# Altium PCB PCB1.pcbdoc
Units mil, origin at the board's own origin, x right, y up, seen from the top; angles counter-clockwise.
Board outline 2870.7 x 2332.93 mil, 2 copper layers (Top Layer, Bottom Layer); 40 components, 64 nets, 418 pads, 3 vias.
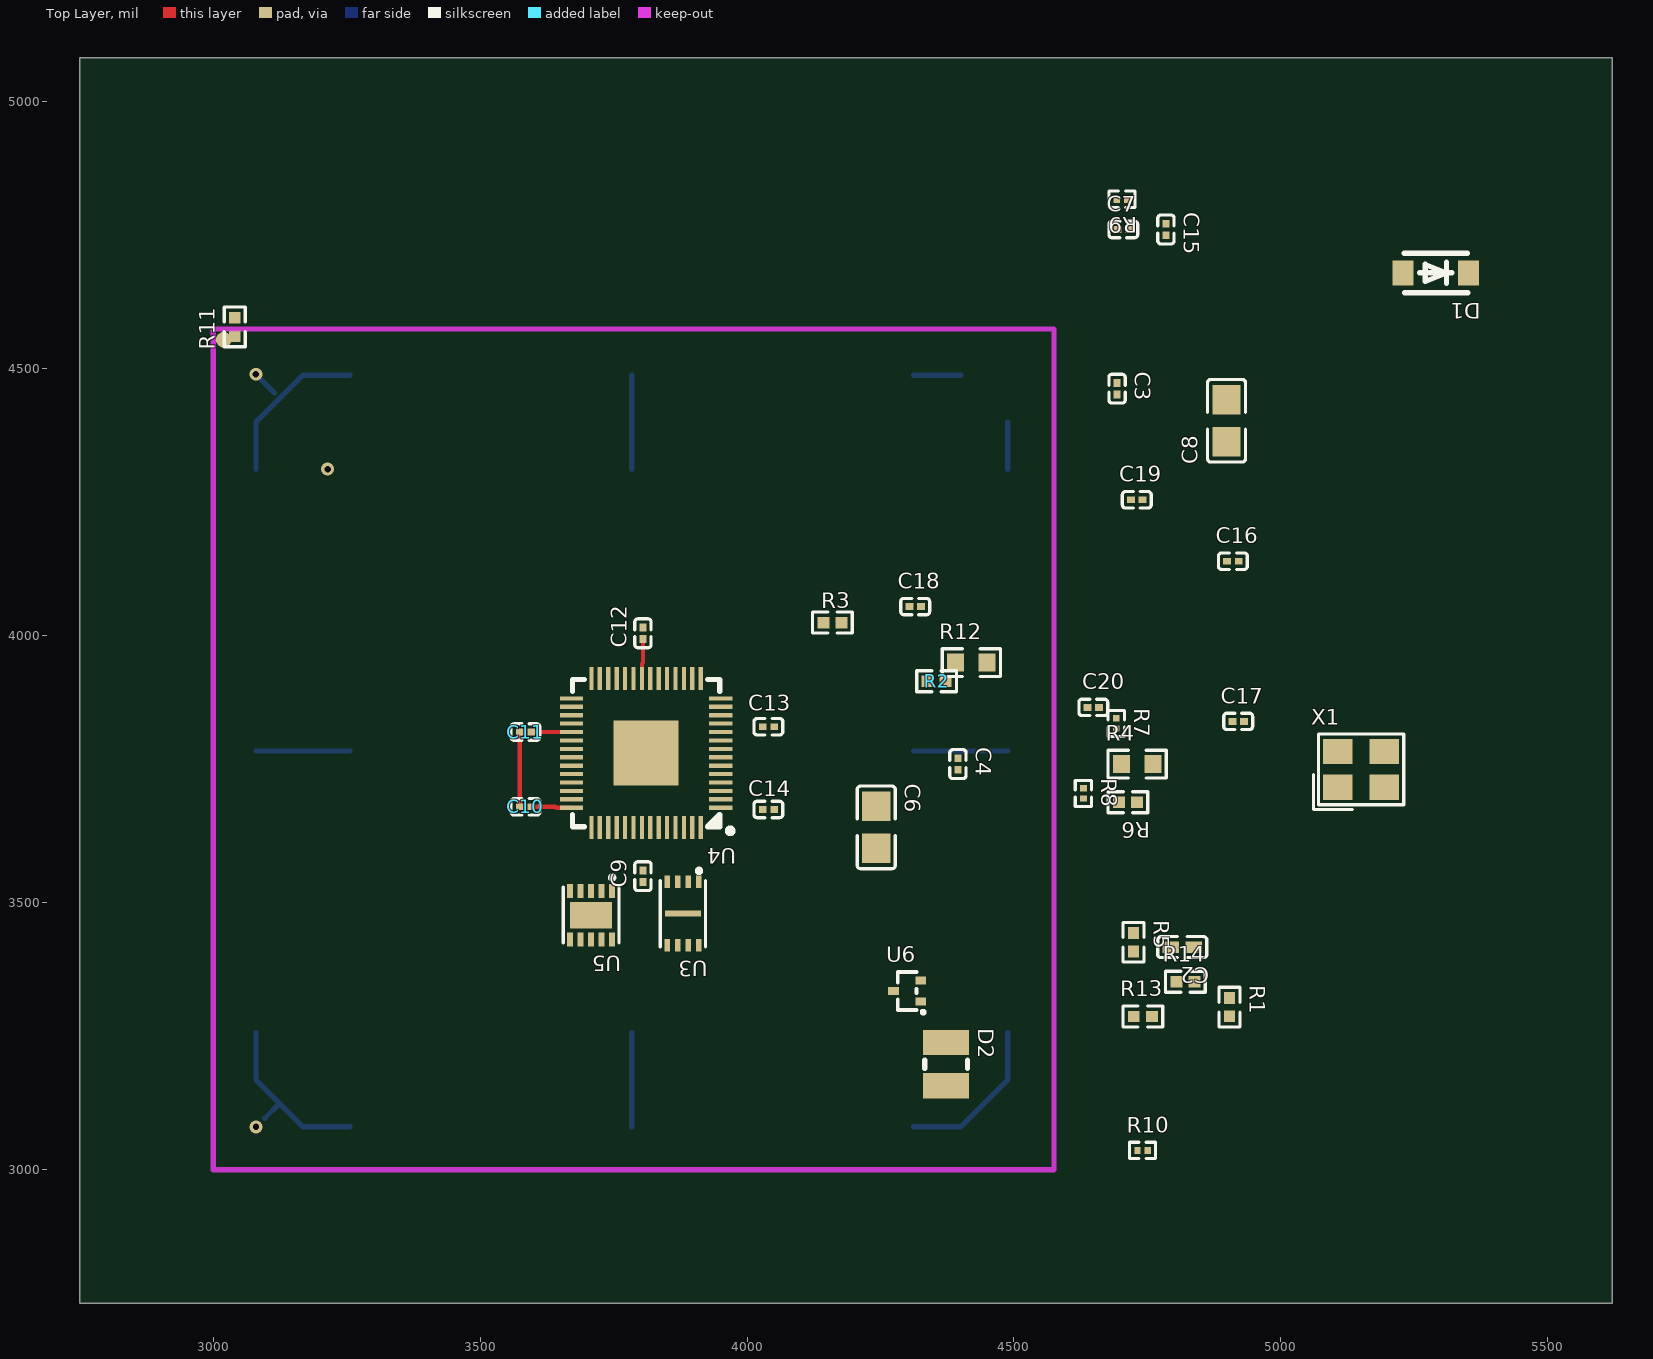
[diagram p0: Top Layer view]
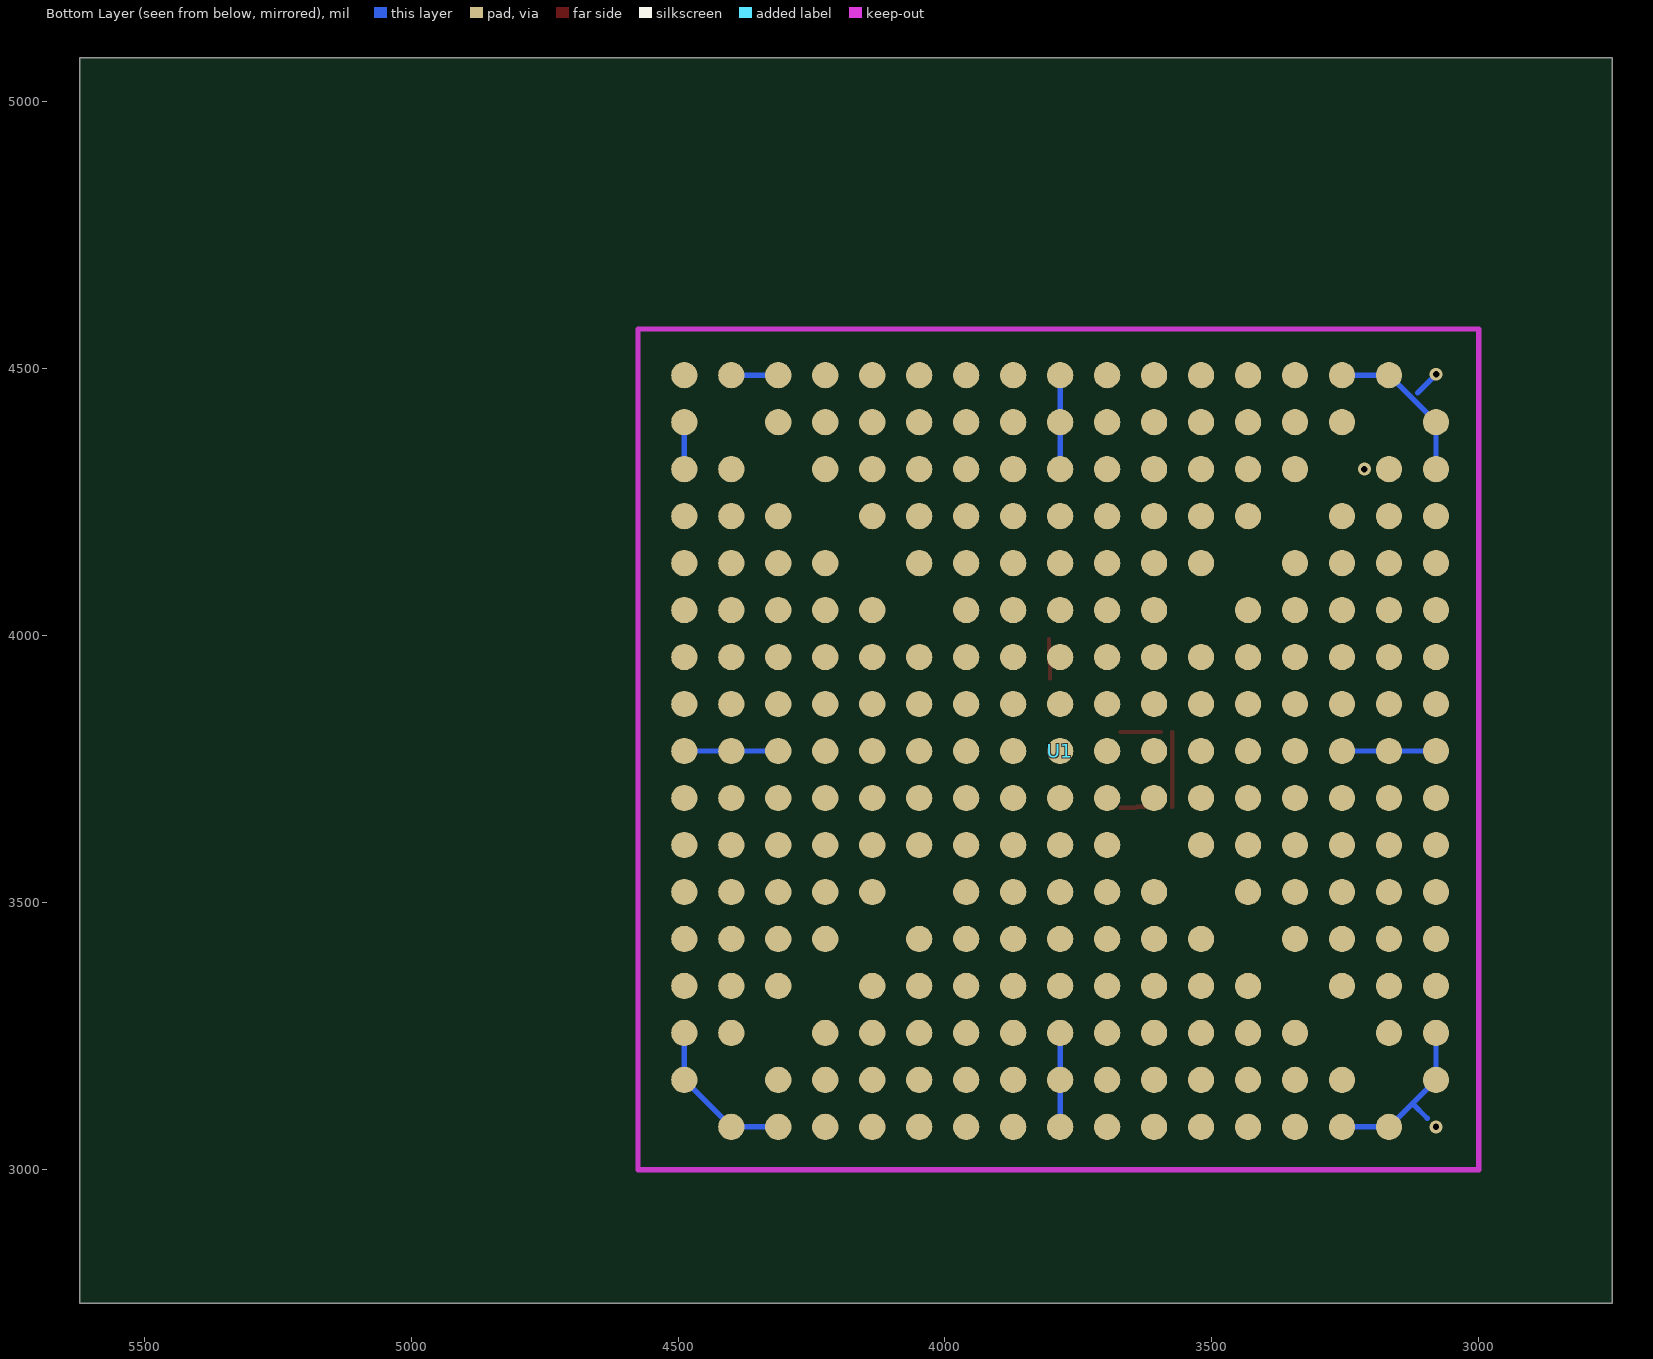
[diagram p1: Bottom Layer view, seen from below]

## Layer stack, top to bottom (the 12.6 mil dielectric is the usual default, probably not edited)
Top Layer: signal copper (thickness not stored)
Dielectric: dielectric 12.6, FR-4, Dk 4.8
Bottom Layer: signal copper (thickness not stored)

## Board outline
5620.7,2750 2750,2750 2750,5082.93 5620.7,5082.93

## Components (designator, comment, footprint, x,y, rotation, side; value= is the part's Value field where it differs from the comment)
C2 "CL05A225MQ5NSNC" C0402 4815.17,3416.97 r180 top
C3 "CL03C150JA3ANNC" C0201 4693.11,4462.99 r270 top
C4 "CL03C150JA3ANNC" C0201 4395,3759.8 r270 top
C6 "GRM21BR60J476ME01L" C0805 4242.08,3641.19 r270 top
C7 "GRM033R60J104KE19D" C0201 4704.78,4761.11 r0 top
C8 "GRM21BR60J476ME01L" C0805 4898.04,4402.83 r90 top
C9 "GRM033R60J104KE19D" C0201 3805,3549.8 r270 top
C10 "GRM033R60J104KE19D" C0201 3585,3679.8 r180 top
C11 "GRM033R60J104KE19D" C0201 3585,3819.8 r180 top
C12 "GRM033R60J104KE19D" C0201 3805,4004.8 r90 top
C13 "GRM033R60J104KE19D" C0201 4040,3829.8 r0 top
C14 "GRM033R60J104KE19D" C0201 4040,3674.8 r0 top
C15 "GRM033R60J104KE19D" C0201 4784.56,4761.11 r270 top
C16 "GRM033R60J104KE19D" C0201 4910,4139.8 r0 top
C17 "GRM033R60J104KE19D" C0201 4920,3839.8 r0 top
C18 "GRM033R60J104KE19D" C0201 4315,4054.8 r0 top
C19 "GRM033R60J104KE19D" C0201 4730,4254.8 r0 top
C20 "GRM033R71E102KA01D" C0201 4648.55,3866 r180 top
D1 "MBR120VLSFT1G" SOD-123F_L2.8-W1.8-LS3.7-RD 5290,4679.8 r180 top
D2 "SRN2512-2R2M" IND-SMD_L2.5-W2.0 4372.83,3197.93 r270 top
R1 "AECR0402F1K00K9" R0402 4903.66,3304.63 r270 top
R2 "AECR0402F1K00K9" R0402 4355,3914.8 r0 top
R3 "CR0402F5K60Q10Z" R0402 4160,4024.8 r0 top
R4 "0603WAF1002T5E" R0603 4730.78,3759.77 r0 top
R5 "RC0402FR-07100KL" R0402 4723.84,3426.01 r270 top
R6 "RC0402FR-07100KL" R0402 4713.43,3688.45 r180 top
R7 "RC0201FR-0727RL" R0201 4691.63,3835.94 r270 top
R8 "RC0201FR-0727RL" R0201 4630,3704.8 r270 top
R9 "RC0201FR-0727RL" R0201 4702.21,4817.55 r180 top
R10 "RC0201FR-0727RL" R0201 4740.75,3036.19 r0 top
R11 "RC0402FR-071RL" R0402 3040.44,4578.68 r90 top
R12 "RC0603FR-07200RL" R0603 4420,3949.8 r0 top
R13 "RC0402FR-07100KL" R0402 4741.39,3287.08 r0 top
R14 "RC0402FR-07200KL" R0402 4821.17,3352.03 r0 top
U1 "usrp2040v0" 17x17 4488.19,4488.19 r180 bottom
U3 "W25Q16JVUXIQ" USON-8_L3.0-W2.0-P0.50-BL-EP 3880,3479.8 r180 top
U4 "RP2040_C2040" LQFN-56_L7.0-W7.0-P0.4-EP 3810.91,3780.43 r180 top
U5 "RT6150BGQW" WSON-10_L2.5-W2.5-P0.50-BL-EP 3707.93,3476.87 r180 top
U6 "DMG1012T-13" SOT-523-3_L1.6-W0.8-P1.00-LS1.6-BR 4300,3334.8 r0 top
X1 "X322512MMB4SI" CRYSTAL-SMD_4P-L3.2-W2.5-BL 5150,3749.8 r0 top

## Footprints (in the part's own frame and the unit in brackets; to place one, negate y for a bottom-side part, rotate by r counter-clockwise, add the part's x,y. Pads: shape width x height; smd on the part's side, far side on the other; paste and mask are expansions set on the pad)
17x17 [mm]
  round 1.25 smd mask+0.051: BOOTSEL(22.35,-13.41) CPUEN(13.41,-13.41) DEBUGEN(13.41,-22.35) GND(0,-33.525) GND(0,-31.29) GND(0,-4.47) GND(0,-2.235) GND(2.235,-35.76) GND(2.235,0) GND(4.47,-35.76) GND(4.47,0) GND(17.88,-17.879) GND(31.29,-35.76) GND(31.29,0) GND(33.525,-35.76) GND(33.525,0) GND(35.76,-33.525) GND(35.76,-31.29) GND(35.76,-4.47) GND(35.76,-2.235) GPIO0(6.705,0) GPIO1(8.94,0) GPIO2(11.175,0) GPIO3(13.41,0) GPIO4(15.645,0) GPIO5(20.115,0) GPIO6(22.35,0) GPIO7(24.585,0) GPIO8(26.82,0) GPIO9(29.055,0) GPIO10(4.47,-2.235) GPIO11(6.705,-2.235) GPIO12(8.94,-2.235) GPIO13(11.175,-2.235) GPIO14(13.41,-2.235) GPIO15(15.645,-2.235) GPIO16(20.115,-2.235) GPIO17(22.35,-2.235) GPIO18(24.585,-2.235) GPIO19(26.82,-2.235) GPIO20(29.055,-2.235) GPIO21(31.29,-2.235) GPIO22(2.235,-4.47) GPIO23(6.705,-4.47) GPIO24(8.94,-4.47) GPIO25(11.175,-4.47) GPIO26(13.41,-4.47) GPIO27(15.645,-4.47) GPIO28(20.115,-4.47) GPIO29(22.35,-4.47) GPIO30(24.585,-4.47) GPIO31(26.82,-4.47) GPIO32(29.055,-4.47) GPIO33(33.525,-4.47) GPIO34(0,-6.705) GPIO35(2.235,-6.705) GPIO36(4.47,-6.705) GPIO37(8.94,-6.705) GPIO38(11.175,-6.705) GPIO39(13.41,-6.705) GPIO40(15.645,-6.705) GPIO41(17.88,-6.705) GPIO42(20.115,-6.705) GPIO43(22.35,-6.705) GPIO44(24.585,-6.705) GPIO45(26.82,-6.705) GPIO46(31.29,-6.705) GPIO47(33.525,-6.705) GPIO48(35.76,-6.705) GPIO49(13.41,-8.94) GPIO50(17.88,-8.94) GPIO51(33.525,-8.94) GPIO52(0,-8.94) GPIO53(2.235,-8.94) GPIO54(4.47,-8.94) GPIO55(6.705,-8.94) GPIO56(11.175,-8.94) GPIO57(31.29,-8.94) GPIO58(22.35,-8.94) GPIO59(24.585,-8.94) GPIO60(29.055,-8.94) GPIO61(15.645,-8.94) GPIO62(20.115,-8.94) GPIO63(35.76,-8.94) GPIO64(0,-11.175) GPIO65(31.29,-11.175) GPIO66(4.47,-11.175) GPIO67(6.705,-11.175) GPIO68(8.94,-11.175) GPIO69(15.645,-11.175) GPIO70(17.88,-11.175) GPIO71(26.82,-11.175) GPIO72(29.055,-11.175) GPIO73(33.525,-11.175) GPIO74(35.76,-11.175) GPIO75(2.235,-11.175) GPIO76(20.115,-11.175) GPIO77(22.35,-11.175) GPIO78(13.41,-11.175) GPIO79(11.175,-13.41) GPIO80(29.055,-13.41) GPIO81(31.29,-13.41) GPIO82(0,-13.41) GPIO83(6.705,-13.41) GPIO84(8.94,-13.41) GPIO85(15.645,-13.41) GPIO86(17.88,-13.41) GPIO87(24.585,-13.41) GPIO88(26.82,-13.41) GPIO89(33.525,-13.41) GPIO90(35.76,-13.41) GPIO91(2.235,-13.41) GPIO92(4.47,-13.41) GPIO93(20.115,-13.41) GPIO94(11.175,-15.645) GPIO95(13.41,-15.645) GPIO96(29.055,-15.645) GPIO97(31.29,-15.645) GPIO98(0,-15.645) GPIO99(6.705,-15.645) GPIO100(8.94,-15.645) GPIO101(24.585,-15.645) GPIO102(26.82,-15.645) GPIO103(33.525,-15.645) GPIO104(35.76,-15.645) GPIO105(2.235,-15.645) GPIO106(4.47,-15.645) GPIO107(22.35,-15.645) GPIO108(6.705,-17.88) GPIO109(8.94,-17.88) GPIO110(11.175,-17.88) GPIO111(13.41,-17.88) GPIO112(22.35,-17.88) GPIO113(24.585,-17.88) GPIO114(26.82,-17.88) GPIO115(29.055,-17.88) GPIO116(0,-20.115) GPIO117(2.235,-20.115) GPIO118(4.47,-20.115) GPIO119(6.705,-20.115) GPIO120(8.94,-20.115) GPIO121(11.175,-20.115) GPIO122(13.41,-20.115) GPIO123(22.35,-20.115) GPIO124(24.585,-20.115) GPIO125(26.82,-20.115) GPIO126(29.055,-20.115) GPIO127(31.29,-20.115) GPIO128(33.525,-20.115) GPIO129(35.76,-20.115) GPIO130(0,-22.35) GPIO131(2.235,-22.35) GPIO132(4.47,-22.35) GPIO133(6.705,-22.35) GPIO134(8.94,-22.35) GPIO135(11.175,-22.35) GPIO136(15.645,-22.35) GPIO137(17.88,-22.35) GPIO138(20.115,-22.35) GPIO139(24.585,-22.35) GPIO140(26.82,-22.35) GPIO141(29.055,-22.35) GPIO142(31.29,-22.35) GPIO143(33.525,-22.35) GPIO144(35.76,-22.35) GPIO145(0,-24.585) GPIO146(2.235,-24.585) GPIO147(4.47,-24.585) GPIO148(6.705,-24.585) GPIO149(8.94,-24.585) GPIO150(13.41,-24.585) GPIO151(15.645,-24.585) GPIO152(17.88,-24.585) GPIO153(20.115,-24.585) GPIO154(22.35,-24.585) GPIO155(26.82,-24.585) GPIO156(29.055,-24.585) GPIO157(31.29,-24.585) GPIO158(33.525,-24.585) GPIO159(35.76,-24.585) GPIO160(0,-26.82) GPIO161(2.235,-26.82) GPIO162(4.47,-26.82) GPIO163(6.705,-26.82) GPIO164(11.175,-26.82) GPIO165(13.41,-26.82) GPIO166(15.645,-26.82) GPIO167(17.88,-26.82) GPIO168(20.115,-26.82) GPIO169(22.35,-26.82) GPIO170(24.585,-26.82) GPIO171(29.055,-26.82) GPIO172(31.29,-26.82) GPIO173(33.525,-26.82) GPIO174(35.76,-26.82) GPIO175(0,-29.055) GPIO176(2.235,-29.055) GPIO177(4.47,-29.055) GPIO178(8.94,-29.055) GPIO179(13.41,-29.055) GPIO180(15.645,-29.055) GPIO181(17.88,-29.055) GPIO182(20.115,-29.055) GPIO183(22.35,-29.055) GPIO184(24.585,-29.055) GPIO185(26.82,-29.055) GPIO186(31.29,-29.055) GPIO187(33.525,-29.055) GPIO188(35.76,-29.055) GPIO189(11.175,-29.055) GPIO190(2.235,-31.29) GPIO191(6.705,-31.29) GPIO192(11.175,-31.29) GPIO193(13.41,-31.29) GPIO194(15.645,-31.29) GPIO195(20.115,-31.29) GPIO196(22.35,-31.29) GPIO197(24.585,-31.29) GPIO198(26.82,-31.29) GPIO199(29.055,-31.29) GPIO200(33.525,-31.29) GPIO201(8.94,-31.29) GPIO202(4.47,-33.525) GPIO203(6.705,-33.525) GPIO204(8.94,-33.525) GPIO205(11.175,-33.525) GPIO206(13.41,-33.525) GPIO207(15.645,-33.525) GPIO208(20.115,-33.525) GPIO209(22.35,-33.525) GPIO210(24.585,-33.525) GPIO211(26.82,-33.525) GPIO212(29.055,-33.525) GPIO213(31.29,-33.525) GPIO214(6.705,-35.76) GPIO215(8.94,-35.76) GPIO216(11.175,-35.76) GPIO217(13.41,-35.76) GPIO218(15.645,-35.76) GPIO219(20.115,-35.76) GPIO220(22.35,-35.76) GPIO221(24.585,-35.76) GPIO222(26.82,-35.76) GPIO223(29.055,-35.76) STAT(0,0) U0(15.645,-15.644) U1(15.645,-17.879) U2(15.645,-20.114) U3(17.88,-15.645) U4(17.88,-20.114) U5(20.115,-15.644) U6(20.115,-17.879) U7(20.115,-20.114) VCC(0,-17.88) VCC(2.235,-17.88) VCC(4.47,-17.88) VCC(17.88,-35.76) VCC(17.88,-33.525) VCC(17.88,-31.29) VCC(17.88,-4.47) VCC(17.88,-2.235) VCC(17.88,0) VCC(31.29,-17.88) VCC(33.525,-17.88) VCC(35.76,-17.88)
C0201 [mil]
  rect 14.51x12.76 smd paste-3937.01 mask+2: 1(-10.8,0) 2(10.8,0)
  silkscreen extent -27,-15 27,15
C0402 [mm]
  rect 0.79x0.54 smd paste-100 mask+0.051: 1(-0.545,0) 2(0.545,0)
  silkscreen extent -1.17,-0.5 1.17,0.5
C0805 [mm]
  rect 1.41x1.35 smd paste-100 mask+0.051: 1(-1,0) 2(1,0)
  silkscreen extent -1.96,-0.9 1.96,0.9
CRYSTAL-SMD_4P-L3.2-W2.5-BL [mm]
  rect 1.4x1.2 smd paste+0 mask+0.051: 1(-1.1,-0.85) 2(1.1,-0.85) 3(1.1,0.85) 4(-1.1,0.85)
  silkscreen extent -2.26,-1.91 2.03,1.68
IND-SMD_L2.5-W2.0 [mm]
  rect 1.2x2.2 smd paste+0 mask+0.051: 1(1.028,0) 2(-1.028,0)
  silkscreen extent -0.2,-1.02 0.2,1.02
LQFN-56_L7.0-W7.0-P0.4-EP [mm]
  rect 1.1x0.2 smd paste-100 mask+0.05: 1(-3.55,2.6) 2(-3.55,2.2) 3(-3.55,1.8) 4(-3.55,1.4) 5(-3.55,1) 6(-3.55,0.6) 7(-3.55,0.2) 8(-3.55,-0.2) 9(-3.55,-0.6) 10(-3.55,-1) 11(-3.55,-1.4) 12(-3.55,-1.8) 13(-3.55,-2.2) 14(-3.55,-2.6) 29(3.55,-2.6) 30(3.55,-2.2) 31(3.55,-1.8) 32(3.55,-1.4) 33(3.55,-1) 34(3.55,-0.6) 35(3.55,-0.2) 36(3.55,0.2) 37(3.55,0.6) 38(3.55,1) 39(3.55,1.4) 40(3.55,1.8) 41(3.55,2.2) 42(3.55,2.6)
  rect 0.2x1.1 smd paste-100 mask+0.05: 15(-2.6,-3.55) 16(-2.2,-3.55) 17(-1.8,-3.55) 18(-1.4,-3.55) 19(-1,-3.55) 20(-0.6,-3.55) 21(-0.2,-3.55) 22(0.2,-3.55) 23(0.6,-3.55) 24(1,-3.55) 25(1.4,-3.55) 26(1.8,-3.55) 27(2.2,-3.55) 28(2.6,-3.55) 43(2.6,3.55) 44(2.2,3.55) 45(1.8,3.55) 46(1.4,3.55) 47(1,3.55) 48(0.6,3.55) 49(0.2,3.55) 50(-0.2,3.55) 51(-0.6,3.55) 52(-1,3.55) 53(-1.4,3.55) 54(-1.8,3.55) 55(-2.2,3.55) 56(-2.6,3.55)
  rect 3.1x3.1 smd paste-100 mask+0.05: 57(0,0)
  silkscreen extent -4.13,-3.5 3.5,3.83
R0201 [mil]
  rect 11.93x12.76 smd paste-3937.01 mask+2: 1(-9.51,0) 2(9.51,0)
  silkscreen extent -24,-15 24,15
R0402 [mm]
  rect 0.566x0.54 smd paste-100 mask+0.051: 1(-0.433,0) 2(0.433,0)
  silkscreen extent -0.94,-0.5 0.94,0.5
R0603 [mil]
  rect 31.75x34.02 smd paste-3937.01 mask+2: 1(-29.66,0) 2(29.66,0)
  silkscreen extent -55,-26 55,26
SOD-123F_L2.8-W1.8-LS3.7-RD [mm]
  rect 1x1.2 smd paste+0 mask+0.051: 1(-1.55,0) 2(1.55,0)
  silkscreen extent -1.52,-0.93 1.49,0.95
SOT-523-3_L1.6-W0.8-P1.00-LS1.6-BR [mm]
  rect 0.51x0.4 smd paste+0 mask+0.051: 1(0.65,-0.5) 2(0.65,0.5) 3(-0.65,0)
  silkscreen extent -0.45,-1.08 0.83,0.9
USON-8_L3.0-W2.0-P0.50-BL-EP [mm]
  rect 0.28x0.6 smd paste+0 mask+0.051: 1(-0.75,-1.507) 2(-0.25,-1.507) 3(0.25,-1.507) 4(0.75,-1.507) 5(0.75,1.507) 6(0.25,1.507) 7(-0.25,1.507) 8(-0.75,1.507)
  rect 1.7x0.3 smd paste+0 mask+0.051: 9(0,0)
  silkscreen extent -1.08,-2.13 1.08,1.58
WSON-10_L2.5-W2.5-P0.50-BL-EP [mm]
  rect 0.28x0.665 smd paste+0 mask+0.051: 1(-1,-1.157) 2(-0.5,-1.157) 3(0,-1.157) 4(0.5,-1.157) 5(1,-1.157) 6(1,1.157) 7(0.5,1.157) 8(0,1.157) 9(-0.5,1.157) 10(-1,1.157)
  rect 2x1.25 smd paste+0 mask+0.051: 11(0,0)
  silkscreen extent -1.33,-1.89 1.33,1.33

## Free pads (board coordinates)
  round 29.53 smd mask+2.01: 1(3020,4554.8)

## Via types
v1: diameter 24.02, hole 12.01, Top Layer to Bottom Layer, 3 vias

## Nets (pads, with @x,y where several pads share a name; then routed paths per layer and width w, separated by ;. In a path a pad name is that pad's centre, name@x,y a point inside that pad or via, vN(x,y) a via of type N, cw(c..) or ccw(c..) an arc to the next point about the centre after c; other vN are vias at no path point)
0ADC0: U1.GPIO89 U4.38
0ADC1: U1.GPIO93 U4.39
0ADC2: U1.GPIO97 U4.40
0CPU-U: U1.U0 U4.37
0GP0: U1.GPIO1 U4.2
0GP1: U1.GPIO5 U4.3
0GP2: U1.GPIO9 U4.4
0GP3: U1.GPIO13 U4.5
0GP4: U1.GPIO17 U4.6
0GP5: U1.GPIO21 U4.7
0GP6: U1.GPIO25 U4.8
0GP7: U1.GPIO29 U4.9
0GP8: U1.GPIO33 U4.11
0GP9: U1.GPIO37 U4.12
0GP10: U1.GPIO41 U4.13
0GP11: U1.GPIO45 U4.14
0GP12: U1.GPIO49 U4.15
0GP13: U1.GPIO53 U4.16
0GP14: U1.GPIO57 U4.17
0GP15: U1.GPIO61 U4.18
0GP16: U1.GPIO65 U4.27
0GP17: U1.GPIO69 U4.28
0GP18: U1.GPIO73 U4.29
0GP19: U1.GPIO77 U4.30
0GP20: U1.GPIO81 U4.31
0GP21: U1.GPIO85 U4.32
0GP22: U4.34
0GPIO23: R6.2 U4.35 U5.7
0GPIO24: R3.1 R4.1 U4.36
0USB0: R7.1 U4.47
0USB1: R9.1 U4.46
0USBDM: R9.2
0USBDP: R7.2
1USBDM: R8.2
1USBDP: R10.2
1V10: C15.2 C16.1 C18.2 U4.23 U4.45 U4.50
$1N4788: R5.1 U5.6
$1N5001: D2.1 U5.4
$1N5005: D2.2 U5.2
$1N10544: C3.2 R1.1 X1.1
$1N11543: R11.2 R12.2 U4.43
$1N11617: C19.2 R11.1
$1N11853: U4.41 U6.2
$1N12009: C20.2 R13.2 R14.1 U6.3
AVCC: D1.2 R3.2 U1.VCC | length 703.9
  Bottom Layer w10: U1.VCC@3080.32,3784.25 3168.31,3784.25 U1.VCC@3256.3,3784.25 ; U1.VCC@3784.25,3080.31 3784.25,3168.31 U1.VCC@3784.25,3256.3 ; U1.VCC@3784.25,4312.2 3784.25,4400.2 U1.VCC@3784.25,4488.19 ; U1.VCC@4312.2,3784.25 4400.2,3784.25 U1.VCC@4488.19,3784.25
BOOTSEL_FOOT: R2.2 U1.BOOTSEL
BOOTSEL_TO_EEPROM: C6.2 D1.1 R2.1 R5.2 R14.2 U3.7 U4.51 U5.5 U5.8
CPUENX: U1.CPUEN U4.26
EPCLK0: U3.6 U4.52
EPSD00: U3.5 U4.53
EPSD10: U3.2 U4.55
EPSD20: U3.3 U4.54
EPSS0: U3.1 U4.56
GND: C2.2 C3.1 C4.1 C6.1 C7.1 C8.2 C9.2 C10.2 C11.2 C12.2 C13.2 C14.2 C15.1 C16.2 C17.1 C18.1 C19.1 C20.1 R4.2 R6.1 R13.1 U1.GND U3.4 U4.19 U4.57 U5.3 U5.9 U5.11 X1.2 X1.4 | length 1256.5
  Top Layer w7.87: C10.2 C11.2
  Bottom Layer w10: U1.GND@3080.32,3256.3 3080.32,3168.31 3124.41,3124.21 ; U1.GND@3080.32,4312.2 3080.32,4400.2 3168.31,4488.19 U1.GND@3256.3,4488.19 ; 3096.63,3096.43 3124.41,3124.21 ; U1.GND@3256.3,3080.31 3168.31,3080.31 3124.41,3124.21 ; U1.GND@4312.2,3080.31 4400.2,3080.31 4488.19,3168.31 U1.GND@4488.19,3256.3 ; U1.GND@4312.2,4488.19 U1.GND@4400.2,4488.19 ; U1.GND@4488.19,4312.2 U1.GND@4488.19,4400.2
IOVDD00: C9.1 U4.49
IOVDD01: C10.1 U4.42 | length 76.1
  Top Layer w7.87: C10.1 3640.78,3679.8 3642.52,3678.07 U4.42
IOVDD02: C11.1 U4.33 | length 75.3
  Top Layer w7.87: C11.1 U4.33
IOVDD03: C12.1 U4.22 | length 74.6
  Top Layer w7.87: U4.22 3803.04,3947.75 3805,3949.71 C12.1
IOVDD04: C13.1 U4.10
IOVDD05: C14.1 U4.1 U4.48
VCC0: C2.1 C7.2 C8.1 C17.2 R12.1 U3.8 U4.44 U5.1 U5.10 U6.1
XIN0: C4.2 U4.20 X1.3
XOUT0: R1.2 U4.21
"": pad.1 R8.1 R10.1 U1.DEBUGEN U1.GPIO0 U1.GPIO2 U1.GPIO3 U1.GPIO4 U1.GPIO6 U1.GPIO7 U1.GPIO8 U1.GPIO10 U1.GPIO11 U1.GPIO12 U1.GPIO14 U1.GPIO15 U1.GPIO16 U1.GPIO18 U1.GPIO19 U1.GPIO20 U1.GPIO22 U1.GPIO23 U1.GPIO24 U1.GPIO26 U1.GPIO27 U1.GPIO28 U1.GPIO30 U1.GPIO31 U1.GPIO32 U1.GPIO34 U1.GPIO35 U1.GPIO36 U1.GPIO38 U1.GPIO39 U1.GPIO40 U1.GPIO42 U1.GPIO43 U1.GPIO44 U1.GPIO46 U1.GPIO47 U1.GPIO48 U1.GPIO50 U1.GPIO51 U1.GPIO52 U1.GPIO54 U1.GPIO55 U1.GPIO56 U1.GPIO58 U1.GPIO59 U1.GPIO60 U1.GPIO62 U1.GPIO63 U1.GPIO64 U1.GPIO66 U1.GPIO67 U1.GPIO68 U1.GPIO70 U1.GPIO71 U1.GPIO72 U1.GPIO74 U1.GPIO75 U1.GPIO76 U1.GPIO78 U1.GPIO79 U1.GPIO80 U1.GPIO82 U1.GPIO83 U1.GPIO84 U1.GPIO86 U1.GPIO87 U1.GPIO88 U1.GPIO90 U1.GPIO91 U1.GPIO92 U1.GPIO94 U1.GPIO95 U1.GPIO96 U1.GPIO98 U1.GPIO99 U1.GPIO100 U1.GPIO101 U1.GPIO102 U1.GPIO103 U1.GPIO104 U1.GPIO105 U1.GPIO106 U1.GPIO107 U1.GPIO108 U1.GPIO109 U1.GPIO110 U1.GPIO111 U1.GPIO112 U1.GPIO113 U1.GPIO114 U1.GPIO115 U1.GPIO116 U1.GPIO117 U1.GPIO118 U1.GPIO119 U1.GPIO120 U1.GPIO121 U1.GPIO122 U1.GPIO123 U1.GPIO124 U1.GPIO125 U1.GPIO126 U1.GPIO127 U1.GPIO128 U1.GPIO129 U1.GPIO130 U1.GPIO131 U1.GPIO132 U1.GPIO133 U1.GPIO134 U1.GPIO135 U1.GPIO136 U1.GPIO137 U1.GPIO138 U1.GPIO139 U1.GPIO140 U1.GPIO141 U1.GPIO142 U1.GPIO143 U1.GPIO144 U1.GPIO145 U1.GPIO146 U1.GPIO147 U1.GPIO148 U1.GPIO149 U1.GPIO150 U1.GPIO151 U1.GPIO152 U1.GPIO153 U1.GPIO154 U1.GPIO155 U1.GPIO156 U1.GPIO157 U1.GPIO158 U1.GPIO159 U1.GPIO160 U1.GPIO161 U1.GPIO162 U1.GPIO163 U1.GPIO164 U1.GPIO165 U1.GPIO166 U1.GPIO167 U1.GPIO168 U1.GPIO169 U1.GPIO170 U1.GPIO171 U1.GPIO172 U1.GPIO173 U1.GPIO174 U1.GPIO175 U1.GPIO176 U1.GPIO177 U1.GPIO178 U1.GPIO179 U1.GPIO180 U1.GPIO181 U1.GPIO182 U1.GPIO183 U1.GPIO184 U1.GPIO185 U1.GPIO186 U1.GPIO187 U1.GPIO188 U1.GPIO189 U1.GPIO190 U1.GPIO191 U1.GPIO192 U1.GPIO193 U1.GPIO194 U1.GPIO195 U1.GPIO196 U1.GPIO197 U1.GPIO198 U1.GPIO199 U1.GPIO200 U1.GPIO201 U1.GPIO202 U1.GPIO203 U1.GPIO204 U1.GPIO205 U1.GPIO206 U1.GPIO207 U1.GPIO208 U1.GPIO209 U1.GPIO210 U1.GPIO211 U1.GPIO212 U1.GPIO213 U1.GPIO214 U1.GPIO215 U1.GPIO216 U1.GPIO217 U1.GPIO218 U1.GPIO219 U1.GPIO220 U1.GPIO221 U1.GPIO222 U1.GPIO223 U1.STAT U1.U1 U1.U2 U1.U3 U1.U4 U1.U5 U1.U6 U1.U7 U3.9 U4.24 U4.25 | length 1459.3
  Inner2 w10: v1(3080,4489.8) 3080,3080.55 v1(3080.32,3080.23)
  Bottom Layer w10: v1(3080,4489.8) 3115.05,4454.75
  other v1: 3214.35,4312.2

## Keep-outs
Board Outline Layer:
  lines w10 net "": 3000,3000 4574.8,3000 4574.8,4574.8 3000,4574.8 3000,3000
